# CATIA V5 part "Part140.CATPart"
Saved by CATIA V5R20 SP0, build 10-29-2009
Part number: DFA 084700-3
Revision: ANY
Definition: UNKNOWN
Nomenclature: DFA 084700-3
Source: Unknown
Bounding box of the stored display mesh (mm): x -2.687 to 2.687, y -2.475 to 2.475, z -2.5 to 2.5
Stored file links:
  C:\Users\Utente\Desktop\IO LAVORO\3D X SITO CF\CUMSA\3D files FA\FA 084712-21\Part140.CATPart

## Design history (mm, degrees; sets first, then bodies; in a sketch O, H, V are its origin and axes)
Body1 "Chaflán4" (main body)
  Solid1: solid without history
